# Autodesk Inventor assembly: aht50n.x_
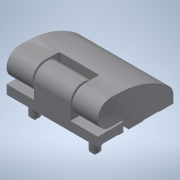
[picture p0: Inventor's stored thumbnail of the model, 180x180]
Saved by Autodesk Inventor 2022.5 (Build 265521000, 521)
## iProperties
Created: 2019-12
Part Number: aht50n.x_
Material: 一般
Document SubType Name: Assembly
Designer: ImaoCorp
Sending System: SOLIDWORKS 2018-2018316
MC: AMD64
MC_MODEL: Intel64 Family 6 Model 60 Stepping 3, GenuineIntel
OS: Windows_NT
FRU: Parasolid Version 30.0, build 310,  6- 8-2018
FORMAT: text
GUISE: transmit
KEY: aht50n
FILE: aht50n.x_t
DATE: Wed Dec 11 13:24:24 2019
Author: ImaoCorp
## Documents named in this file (6)
- X:\14_SW2022-Inv2022\00_全2023-1023新製品(TCC)まで\a\aht50n\AHT50N.iam
- X:\14_SW2022-Inv2022\00_全2023-1023新製品(TCC)まで\a\aht50n\aht50n_01.ipt
- X:\14_SW2022-Inv2022\00_全2023-1023新製品(TCC)まで\a\aht50n\aht50n_02.ipt
- X:\14_SW2022-Inv2022\00_全2023-1023新製品(TCC)まで\a\aht50n\aht50n_03.ipt
- X:\14_SW2022-Inv2022\00_全2023-1023新製品(TCC)まで\a\aht50n\aht50n_04.ipt
- X:\14_SW2022-Inv2022\00_全2023-1023新製品(TCC)まで\a\aht50n\aht50n_05.ipt
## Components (5 placed, 5 different names)
1. aht50n_01
2. aht50n_02
3. aht50n_03
4. aht50n_04
5. aht50n_05
